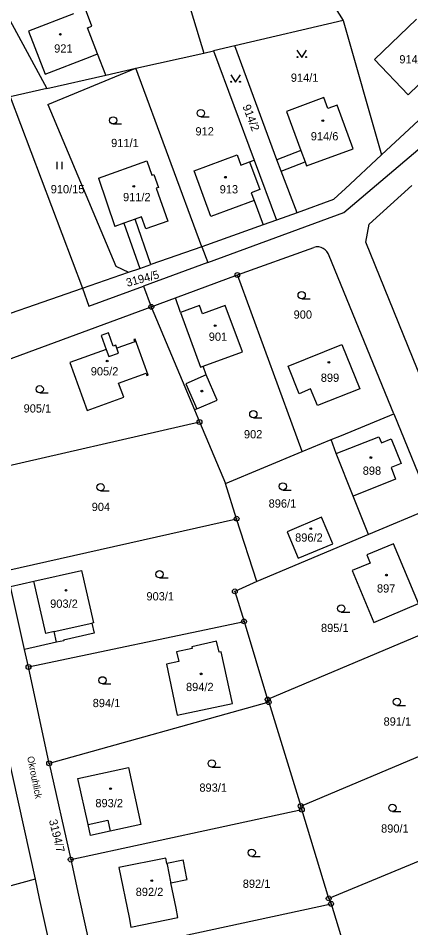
# Model space of a CAD drawing. Extents: x -736345 to -729997, y -1130177 to -1122501.
# Drawn here: x -733191.4 to -733110.4, y -1127674.1 to -1127486.6 of the extents above; entities that cross this region are included whole.
import ezdxf

# ---------------------------------------------------------------- set-up
doc = ezdxf.new("R2010")
doc.units = 0
for name, color, linetype in [('Vrstva 1', 7, 'Continuous'), ('Vrstva 15', 7, 'Continuous'), ('Vrstva 18', 7, 'Continuous'), ('Vrstva 19', 7, 'Continuous'), ('Vrstva 25', 7, 'Continuous'), ('Vrstva 4', 7, 'Continuous')]:
    doc.layers.add(name, color=color, linetype=linetype)

msp = doc.modelspace()

# ---------------------------------------------------------------- linework, layer by layer
at = {"layer": 'Vrstva 1'}
for points in [[(-733162.57, -1127462.54), (-733153.08, -1127493.77)], [(-733200.3, -1127473.75), (-733185.45, -1127501.06)], [(-733131.59, -1127475.55), (-733124.39, -1127487.07)], [(-733176.16, -1127488.24), (-733177.51, -1127484.73)], [(-733177.08, -1127488.59), (-733176.16, -1127488.24)], [(-733124.39, -1127487.07), (-733146.75, -1127492.31)], [(-733124.39, -1127487.07), (-733116.47, -1127514.77)], [(-733117.93, -1127495.12), (-733109.26, -1127486.8)], [(-733175.03, -1127493.96), (-733177.08, -1127488.59)], [(-733167.12, -1127496.9), (-733153.08, -1127493.77)], [(-733153.08, -1127493.77), (-733151.13, -1127493.34)], [(-733146.75, -1127492.31), (-733151.13, -1127493.34)], [(-733151.13, -1127493.34), (-733142.71, -1127515.87)], [(-733138.06, -1127515.78), (-733146.75, -1127492.31)], [(-733124.28, -1127526.63), (-733100.48, -1127506.47), (-733086.33, -1127493.47), (-733083.64, -1127496.47)], [(-733173.29, -1127498.3), (-733175.03, -1127493.96)], [(-733111.01, -1127502.35), (-733117.93, -1127495.12)], [(-733102.33, -1127494.03), (-733111.01, -1127502.35)], [(-733185.28, -1127504.4), (-733167.12, -1127496.9)], [(-733173.29, -1127498.3), (-733167.12, -1127496.9)], [(-733153.51, -1127533.7), (-733167.12, -1127496.9)], [(-733116.47, -1127514.77), (-733097.43, -1127497.12)], [(-733185.45, -1127501.06), (-733173.29, -1127498.3)], [(-733185.45, -1127501.06), (-733193.06, -1127502.79)], [(-733193.06, -1127502.79), (-733178.14, -1127542.26)], [(-733128.38, -1127502.96), (-733136.07, -1127505.79)], [(-733127.55, -1127505.2), (-733128.38, -1127502.96)], [(-733185.28, -1127504.4), (-733171.22, -1127537.7)], [(-733125.64, -1127504.49), (-733127.55, -1127505.2)], [(-733122.3, -1127513.53), (-733125.64, -1127504.49)], [(-733136.07, -1127505.79), (-733133.1, -1127513.84)], [(-733133.1, -1127513.84), (-733138.06, -1127515.78)], [(-733131.93, -1127517.02), (-733122.3, -1127513.53)], [(-733174.85, -1127519.53), (-733164.89, -1127516)], [(-733164.89, -1127516), (-733163.84, -1127518.97)], [(-733155.11, -1127518.08), (-733146.21, -1127514.78)], [(-733146.21, -1127514.78), (-733145.46, -1127516.86)], [(-733145.46, -1127516.86), (-733143.68, -1127516.22)], [(-733143.68, -1127516.22), (-733142.71, -1127515.87)], [(-733142.71, -1127515.87), (-733138.12, -1127528.19)], [(-733137.19, -1127518.13), (-733138.06, -1127515.78)], [(-733137.19, -1127518.13), (-733132.24, -1127516.18)], [(-733132.24, -1127516.18), (-733131.93, -1127517.02)], [(-733116.47, -1127514.77), (-733123.98, -1127521.74)], [(-733151.65, -1127527.46), (-733155.11, -1127518.08)], [(-733133.89, -1127526.67), (-733137.19, -1127518.13)], [(-733174.85, -1127519.53), (-733171.43, -1127529.49)], [(-733163.84, -1127518.97), (-733163.41, -1127518.82)], [(-733163.41, -1127518.82), (-733162.48, -1127521.45)], [(-733162.48, -1127521.45), (-733162.91, -1127521.6)], [(-733162.91, -1127521.6), (-733160.5, -1127528.42)], [(-733123.98, -1127521.74), (-733125.44, -1127523.08)], [(-733119, -1127529.07), (-733110.24, -1127521.07)], [(-733125.44, -1127523.08), (-733126.39, -1127523.96)], [(-733142.75, -1127524.17), (-733151.65, -1127527.46)], [(-733142.75, -1127524.17), (-733140.91, -1127529.19)], [(-733126.39, -1127523.96), (-733133.89, -1127526.67)], [(-733165.93, -1127527.5), (-733167.29, -1127527.99)], [(-733165.03, -1127530.03), (-733165.93, -1127527.5)], [(-733152.28, -1127536.92), (-733124.28, -1127526.63)], [(-733133.89, -1127526.67), (-733138.12, -1127528.19)], [(-733169.62, -1127528.83), (-733171.43, -1127529.49)], [(-733169.62, -1127528.83), (-733166.33, -1127538.16)], [(-733164.04, -1127537.36), (-733167.29, -1127527.99)], [(-733160.5, -1127528.42), (-733165.03, -1127530.03)], [(-733140.91, -1127529.19), (-733153.51, -1127533.7)], [(-733138.12, -1127528.19), (-733140.91, -1127529.19)], [(-733119.72, -1127532.75), (-733119, -1127529.07)], [(-733107.12, -1127563.71), (-733119.72, -1127532.75)], [(-733153.51, -1127533.7), (-733164.04, -1127537.36)], [(-733153.51, -1127533.7), (-733152.28, -1127536.92)], [(-733146.19, -1127539.51), (-733130.41, -1127533.84)], [(-733152.28, -1127536.92), (-733165.55, -1127541.8)], [(-733113.93, -1127568.12), (-733127.3, -1127535.54)], [(-733171.22, -1127537.7), (-733168.62, -1127538.95)], [(-733168.62, -1127538.95), (-733166.33, -1127538.16)], [(-733166.33, -1127538.16), (-733164.04, -1127537.36)], [(-733178.14, -1127542.26), (-733168.62, -1127538.95)], [(-733158.97, -1127544.24), (-733146.19, -1127539.51)], [(-733134.88, -1127570.27), (-733146.19, -1127539.51)], [(-733202.72, -1127550.77), (-733178.14, -1127542.26)], [(-733178.14, -1127542.26), (-733176.83, -1127545.95), (-733165.55, -1127541.8)], [(-733165.55, -1127541.8), (-733163.94, -1127546.08)], [(-733163.94, -1127546.08), (-733158.97, -1127544.24)], [(-733157.93, -1127547.25), (-733158.97, -1127544.24)], [(-733200.69, -1127559.59), (-733163.94, -1127546.08)], [(-733163.94, -1127546.08), (-733155.05, -1127567.34)], [(-733154, -1127545.82), (-733157.93, -1127547.25)], [(-733153.39, -1127547.5), (-733154, -1127545.82)], [(-733148.68, -1127545.79), (-733153.39, -1127547.5)], [(-733145.16, -1127555.35), (-733148.68, -1127545.79)], [(-733172.77, -1127551.42), (-733174.27, -1127551.96)], [(-733174.27, -1127551.96), (-733173.23, -1127554.88)], [(-733171.77, -1127554.2), (-733172.77, -1127551.42)], [(-733167.33, -1127553.29), (-733171.04, -1127554.62)], [(-733167.27, -1127552.74), (-733167.51, -1127552.82)], [(-733167.51, -1127552.82), (-733167.33, -1127553.29)], [(-733164.6, -1127560.14), (-733167.27, -1127552.74)], [(-733135.71, -1127558.32), (-733124.64, -1127553.88)], [(-733124.64, -1127553.88), (-733120.92, -1127562.96)], [(-733173.23, -1127554.88), (-733180.72, -1127557.57)], [(-733171.26, -1127554.01), (-733171.77, -1127554.2)], [(-733171.04, -1127554.62), (-733171.26, -1127554.01)], [(-733153.26, -1127558.33), (-733145.16, -1127555.35)], [(-733180.72, -1127557.57), (-733177.18, -1127567.42)], [(-733152.64, -1127560.13), (-733153.26, -1127558.33)], [(-733133.43, -1127563.99), (-733135.71, -1127558.32)], [(-733170.67, -1127561.79), (-733165, -1127559.75)], [(-733165, -1127559.75), (-733164.83, -1127560.23)], [(-733164.83, -1127560.23), (-733164.6, -1127560.14)], [(-733150.39, -1127565.32), (-733152.64, -1127560.13)], [(-733169.62, -1127564.71), (-733170.67, -1127561.79)], [(-733131.1, -1127563.01), (-733133.43, -1127563.99)], [(-733129.65, -1127566.44), (-733131.1, -1127563.01)], [(-733120.92, -1127562.96), (-733129.65, -1127566.44)], [(-733177.18, -1127567.42), (-733169.62, -1127564.71)], [(-733154.56, -1127567.13), (-733150.39, -1127565.32)], [(-733154.56, -1127567.13), (-733155.05, -1127567.34)], [(-733155.05, -1127567.34), (-733154.01, -1127569.82)], [(-733124.74, -1127572.58), (-733113.93, -1127568.12)], [(-733113.93, -1127568.12), (-733106.06, -1127587.54)], [(-733198.38, -1127579.97), (-733154.01, -1127569.82)], [(-733154.01, -1127569.82), (-733148.61, -1127582.52)], [(-733132.81, -1127575.91), (-733134.88, -1127570.27)], [(-733126.87, -1127573.46), (-733124.74, -1127572.58)], [(-733132.81, -1127575.91), (-733126.87, -1127573.46)], [(-733125.85, -1127576.3), (-733126.87, -1127573.46)], [(-733148.61, -1127582.52), (-733132.81, -1127575.91)], [(-733122.35, -1127585.14), (-733125.85, -1127576.3)], [(-733146.35, -1127589.76), (-733148.61, -1127582.52)], [(-733119.16, -1127593.03), (-733122.35, -1127585.14)], [(-733106.06, -1127587.54), (-733119.16, -1127593.03)], [(-733128.86, -1127589.42), (-733135.95, -1127592.43)], [(-733126.55, -1127594.92), (-733128.86, -1127589.42)], [(-733193.69, -1127600.46), (-733146.35, -1127589.76)], [(-733142.18, -1127602.68), (-733146.35, -1127589.76)], [(-733119.16, -1127593.03), (-733142.18, -1127602.68)], [(-733135.95, -1127592.43), (-733133.65, -1127597.91)], [(-733133.65, -1127597.91), (-733126.55, -1127594.92)], [(-733114.04, -1127594.94), (-733119.54, -1127597.23)], [(-733108.83, -1127607.22), (-733114.04, -1127594.94)], [(-733119.54, -1127597.23), (-733118.84, -1127598.9)], [(-733188.13, -1127602.62), (-733178.29, -1127600.41)], [(-733178.29, -1127600.41), (-733175.86, -1127611.22)], [(-733118.84, -1127598.9), (-733122.55, -1127600.46)], [(-733122.55, -1127600.46), (-733118.04, -1127611.12)], [(-733192.96, -1127603.71), (-733188.13, -1127602.62)], [(-733190.05, -1127616.7), (-733192.96, -1127603.71)], [(-733142.18, -1127602.68), (-733146.73, -1127604.74)], [(-733146.73, -1127604.74), (-733144.82, -1127610.93)], [(-733118.04, -1127611.12), (-733108.83, -1127607.22)], [(-733189.24, -1127620.32), (-733144.82, -1127610.93)], [(-733175.86, -1127611.22), (-733176.16, -1127611.29)], [(-733176.16, -1127611.29), (-733175.7, -1127613.34)], [(-733144.82, -1127610.93), (-733139.96, -1127627.02)], [(-733175.7, -1127613.34), (-733182.01, -1127614.81)], [(-733106.94, -1127613.06), (-733139.96, -1127627.02)], [(-733183.46, -1127615.23), (-733190.05, -1127616.7)], [(-733181.99, -1127614.9), (-733183.46, -1127615.23)], [(-733182.01, -1127614.81), (-733181.99, -1127614.9)], [(-733150.47, -1127614.99), (-733155.6, -1127616.16)], [(-733149.95, -1127617.28), (-733150.47, -1127614.99)], [(-733189.24, -1127620.32), (-733190.05, -1127616.7)], [(-733155.53, -1127616.48), (-733158.74, -1127617.21)], [(-733158.74, -1127617.21), (-733158.29, -1127619.19)], [(-733155.6, -1127616.16), (-733155.53, -1127616.48)], [(-733149.5, -1127617.18), (-733149.95, -1127617.28)], [(-733147.23, -1127627.82), (-733149.5, -1127617.18)], [(-733158.29, -1127619.19), (-733160.81, -1127619.76)], [(-733185, -1127640.19), (-733189.24, -1127620.32)], [(-733160.81, -1127619.76), (-733158.62, -1127630.26)], [(-733139.73, -1127627.59), (-733185, -1127640.19)], [(-733158.62, -1127630.26), (-733147.23, -1127627.82)], [(-733139.96, -1127627.02), (-733139.73, -1127627.59)], [(-733139.73, -1127627.59), (-733133.13, -1127648.99)], [(-733133.13, -1127648.99), (-733088.65, -1127630.27)], [(-733193.7, -1127637.64), (-733187.89, -1127664.09)], [(-733185, -1127640.19), (-733180.54, -1127660.03)], [(-733179.06, -1127643.33), (-733168.66, -1127641.05)], [(-733168.66, -1127641.05), (-733166.07, -1127652.77)], [(-733176.98, -1127652.82), (-733179.06, -1127643.33)], [(-733132.91, -1127649.73), (-733133.13, -1127648.99)], [(-733180.54, -1127660.03), (-733132.91, -1127649.73)], [(-733127.36, -1127668.03), (-733132.91, -1127649.73)], [(-733176.49, -1127655.09), (-733176.98, -1127652.82)], [(-733166.07, -1127652.77), (-733172.43, -1127654.19)], [(-733172.43, -1127654.19), (-733176.49, -1127655.09)], [(-733094.98, -1127654.63), (-733127.36, -1127668.03)], [(-733180.54, -1127660.03), (-733178.93, -1127667.37)], [(-733160.95, -1127659.7), (-733170.63, -1127661.68)], [(-733160.73, -1127660.81), (-733160.95, -1127659.7)], [(-733157.37, -1127660.13), (-733160.73, -1127660.81)], [(-733157.32, -1127660.37), (-733157.37, -1127660.13)], [(-733156.6, -1127663.9), (-733157.32, -1127660.37)], [(-733170.63, -1127661.68), (-733168.52, -1127671.99)], [(-733187.89, -1127664.09), (-733218.48, -1127672.45)], [(-733187.89, -1127664.09), (-733187.02, -1127668.07)], [(-733159.91, -1127664.83), (-733156.55, -1127664.14)], [(-733156.55, -1127664.14), (-733156.6, -1127663.9)], [(-733158.84, -1127670.01), (-733159.91, -1127664.83)], [(-733187.02, -1127668.07), (-733183.35, -1127684.78)], [(-733178.93, -1127667.37), (-733176.21, -1127679.8)], [(-733127.36, -1127668.03), (-733126.88, -1127669.14)], [(-733176.21, -1127679.8), (-733126.88, -1127669.14)], [(-733158.45, -1127671.97), (-733158.84, -1127670.01)], [(-733126.88, -1127669.14), (-733121.37, -1127687.19)], [(-733168.52, -1127671.99), (-733168.13, -1127673.94)], [(-733168.13, -1127673.94), (-733158.45, -1127671.97)]]:
    msp.add_lwpolyline(points, dxfattribs=at)
msp.add_arc((-733129.668, -1127536.178), 2.453, 15.02838, 107.60849, dxfattribs=at)
at = {"layer": 'Vrstva 25'}
for points in [[(-733133.93, -1127493.2), (-733132.93, -1127494.7), (-733131.93, -1127493.2)], [(-733147.55, -1127498.28), (-733146.55, -1127499.78), (-733145.55, -1127498.28)], [(-733153.73, -1127506.9), (-733151.98, -1127506.9)], [(-733171.81, -1127508.39), (-733170.06, -1127508.39)], [(-733183.357, -1127517.695), (-733183.357, -1127516.195)], [(-733182.323, -1127517.695), (-733182.323, -1127516.195)], [(-733132.94, -1127544.44), (-733131.19, -1127544.44)], [(-733186.94, -1127563.83), (-733185.19, -1127563.83)], [(-733142.9, -1127568.97), (-733141.15, -1127568.97)], [(-733136.83, -1127583.85), (-733135.08, -1127583.85)], [(-733174.38, -1127584.02), (-733172.63, -1127584.02)], [(-733162.24, -1127601.96), (-733160.49, -1127601.96)], [(-733124.77, -1127609.01), (-733123.02, -1127609.01)], [(-733174, -1127623.82), (-733172.25, -1127623.82)], [(-733113.3, -1127628.25), (-733111.55, -1127628.25)], [(-733151.45, -1127640.98), (-733149.7, -1127640.98)], [(-733114.24, -1127650.12), (-733112.49, -1127650.12)], [(-733143.23, -1127659.36), (-733141.48, -1127659.36)]]:
    msp.add_lwpolyline(points, dxfattribs=at)
for centre, radius in [((-733182.68, -1127489.9), 0.175), ((-733133.83, -1127494.6), 0.1), ((-733132.03, -1127494.6), 0.1), ((-733147.45, -1127499.68), 0.1), ((-733145.65, -1127499.68), 0.1), ((-733171.81, -1127507.64), 0.75), ((-733153.73, -1127506.15), 0.75), ((-733128.58, -1127507.71), 0.175), ((-733148.66, -1127519.36), 0.175), ((-733167.54, -1127521.25), 0.175), ((-733146.19, -1127539.51), 0.5), ((-733146.19, -1127539.51), 0.032), ((-733132.94, -1127543.69), 0.75), ((-733163.94, -1127546.08), 0.5), ((-733163.94, -1127546.08), 0.032), ((-733150.77, -1127549.96), 0.175), ((-733173.03, -1127557.26), 0.175), ((-733127.33, -1127557.53), 0.175), ((-733186.94, -1127563.08), 0.75), ((-733153.52, -1127563.46), 0.175), ((-733142.9, -1127568.22), 0.75), ((-733154.01, -1127569.82), 0.5), ((-733154.01, -1127569.82), 0.032), ((-733118.68, -1127577.15), 0.175), ((-733174.38, -1127583.27), 0.75), ((-733136.83, -1127583.1), 0.75), ((-733146.35, -1127589.76), 0.5), ((-733146.35, -1127589.76), 0.032), ((-733131.07, -1127591.8), 0.175), ((-733162.24, -1127601.21), 0.75), ((-733115.46, -1127601.39), 0.175), ((-733181.51, -1127604.51), 0.175), ((-733146.73, -1127604.74), 0.5), ((-733146.73, -1127604.74), 0.032), ((-733124.77, -1127608.26), 0.75), ((-733144.82, -1127610.93), 0.5), ((-733144.82, -1127610.93), 0.032), ((-733189.24, -1127620.32), 0.5), ((-733189.24, -1127620.32), 0.032), ((-733174, -1127623.07), 0.75), ((-733153.66, -1127621.75), 0.175), ((-733139.96, -1127627.02), 0.5), ((-733139.96, -1127627.02), 0.032), ((-733113.3, -1127627.5), 0.75), ((-733139.73, -1127627.59), 0.5), ((-733139.73, -1127627.59), 0.032), ((-733185, -1127640.19), 0.5), ((-733151.45, -1127640.23), 0.75), ((-733185, -1127640.19), 0.032), ((-733172.34, -1127645.42), 0.175), ((-733133.13, -1127648.99), 0.5), ((-733132.91, -1127649.73), 0.5), ((-733133.13, -1127648.99), 0.032), ((-733114.24, -1127649.37), 0.75), ((-733132.91, -1127649.73), 0.032), ((-733143.23, -1127658.61), 0.75), ((-733180.54, -1127660.03), 0.5), ((-733180.54, -1127660.03), 0.032), ((-733163.83, -1127664.37), 0.175), ((-733127.36, -1127668.03), 0.5), ((-733127.36, -1127668.03), 0.032), ((-733126.88, -1127669.14), 0.5), ((-733126.88, -1127669.14), 0.032)]:
    msp.add_circle(centre, radius, dxfattribs=at)
at = {"layer": 'Vrstva 4'}
for points in [[(-733179.94, -1127485.67), (-733189.28, -1127489.26)], [(-733189.28, -1127489.26), (-733185.78, -1127498.1)], [(-733185.78, -1127498.1), (-733176.53, -1127494.54)], [(-733176.53, -1127494.54), (-733175.03, -1127493.96)], [(-733133.1, -1127513.84), (-733132.24, -1127516.18)], [(-733143.68, -1127516.22), (-733141.59, -1127521.88)], [(-733141.59, -1127521.88), (-733143.37, -1127522.57)], [(-733143.37, -1127522.57), (-733142.75, -1127524.17)], [(-733167.29, -1127527.99), (-733169.62, -1127528.83)], [(-733157.93, -1127547.25), (-733153.82, -1127558.53)], [(-733173.23, -1127554.88), (-733172.69, -1127556.35)], [(-733172.69, -1127556.35), (-733170.67, -1127555.62)], [(-733170.67, -1127555.62), (-733171.04, -1127554.62)], [(-733153.82, -1127558.53), (-733153.26, -1127558.33)], [(-733152.64, -1127560.13), (-733156.8, -1127561.93)], [(-733156.8, -1127561.93), (-733154.56, -1127567.13)], [(-733125.85, -1127576.3), (-733117.06, -1127572.85)], [(-733117.06, -1127572.85), (-733116.5, -1127574.15)], [(-733116.5, -1127574.15), (-733114.48, -1127573.28)], [(-733114.48, -1127573.28), (-733112.46, -1127578.41)], [(-733112.46, -1127578.41), (-733114.5, -1127579.19)], [(-733114.5, -1127579.19), (-733113.59, -1127581.58)], [(-733113.59, -1127581.58), (-733122.35, -1127585.14)], [(-733185.68, -1127613.41), (-733188.13, -1127602.62)], [(-733183.96, -1127613.03), (-733176.16, -1127611.29)], [(-733183.96, -1127613.03), (-733185.68, -1127613.41)], [(-733183.46, -1127615.23), (-733183.96, -1127613.03)], [(-733176.98, -1127652.82), (-733172.9, -1127651.92)], [(-733172.9, -1127651.92), (-733172.43, -1127654.19)], [(-733160.73, -1127660.81), (-733160.68, -1127661.06)], [(-733160.68, -1127661.06), (-733159.95, -1127664.58)], [(-733159.95, -1127664.58), (-733159.91, -1127664.83)]]:
    msp.add_lwpolyline(points, dxfattribs=at)

# ---------------------------------------------------------------- texts
at = {"layer": 'Vrstva 15'}
msp.add_text('Okrouhlick\xa0', height=1.39999, rotation=281.20224, dxfattribs=at).set_placement((-733189.525, -1127638.857))
at = {"layer": 'Vrstva 18'}
for s, p in [('914/1', (-733135.17, -1127499.69)), ('912', (-733154.83, -1127510.75)), ('911/1', (-733172.21, -1127513.15)), ('910/15', (-733184.67, -1127522.68)), ('900', (-733134.6, -1127548.52)), ('905/1', (-733190.26, -1127567.87)), ('902', (-733144.84, -1127573.19)), ('896/1', (-733139.75, -1127587.47)), ('904', (-733176.22, -1127588.17)), ('903/1', (-733164.94, -1127606.6)), ('895/1', (-733128.96, -1127613.12)), ('894/1', (-733176.01, -1127628.6)), ('891/1', (-733116.06, -1127632.41)), ('893/1', (-733154.02, -1127646.04)), ('890/1', (-733116.57, -1127654.47)), ('892/1', (-733145.08, -1127665.85))]:
    msp.add_text(s, height=1.7, dxfattribs=at).set_placement(p)
for s, rotation, p in [('914/2', 291.00231, (-733145.172, -1127504.745)), ('3194/5', 15.00012, (-733168.879, -1127541.966)), ('3194/7', 283.80226, (-733185.039, -1127651.956))]:
    msp.add_text(s, height=1.7, rotation=rotation, dxfattribs=at).set_placement(p)
at = {"layer": 'Vrstva 19'}
for s, p in [('921', (-733183.96, -1127493.67)), ('914/5', (-733112.81, -1127495.9)), ('914/6', (-733131.06, -1127511.77)), ('913', (-733149.84, -1127522.7)), ('911/2', (-733169.77, -1127524.31)), ('901', (-733152.09, -1127553.08)), ('905/2', (-733176.41, -1127560.22)), ('899', (-733129, -1127561.54)), ('898', (-733120.35, -1127580.7)), ('896/2', (-733134.29, -1127594.49)), ('897', (-733117.42, -1127604.98)), ('903/2', (-733184.78, -1127608.12)), ('894/2', (-733156.78, -1127625.29)), ('893/2', (-733175.46, -1127649.23)), ('892/2', (-733167.15, -1127667.53))]:
    msp.add_text(s, height=1.7, dxfattribs=at).set_placement(p)

doc.saveas('drawing.dxf')
